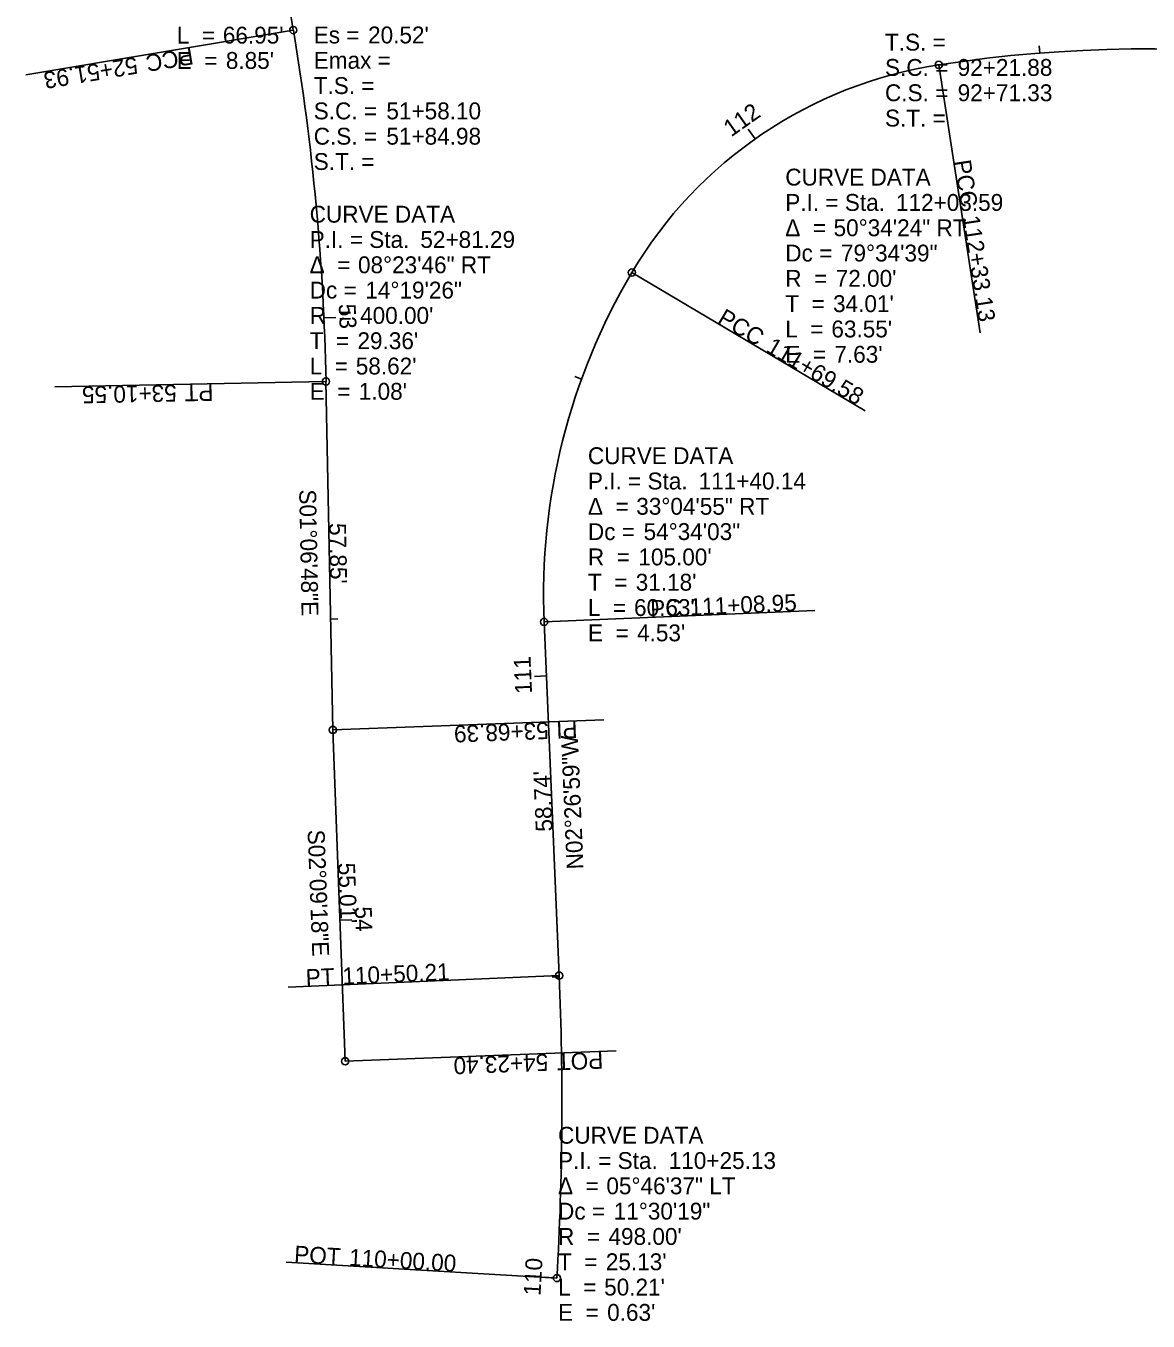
# Model space of a CAD drawing. Extents: x 2047391 to 2047982, y 456752 to 457262.
# Drawn here: x 2047571.9 to 2047758.1, y 456752.1 to 456967.1 of the extents above; entities that cross this region are included whole.
import ezdxf

# ---------------------------------------------------------------- set-up
doc = ezdxf.new("R2010")
doc.units = 0
for name, color, linetype in [('GE_P_Alignment', 7, 'Continuous'), ('GE_P_Alignment_100_Bearings', 7, 'Continuous'), ('GE_P_Alignment_100_Cardinal_Points', 7, 'Continuous'), ('GE_P_Alignment_100_Curve_Data', 7, 'Continuous'), ('GE_P_Alignment_100_Distances', 7, 'Continuous'), ('GE_P_Alignment_100_Stations', 7, 'Continuous')]:
    doc.layers.add(name, color=color, linetype=linetype)

msp = doc.modelspace()

# ---------------------------------------------------------------- linework, layer by layer
at = {"layer": 'GE_P_Alignment'}
for p, q in [((2047621.7, 456908.06), (2047622.83, 456850.23)), ((2047660.4, 456809.46), (2047657.89, 456868.15)), ((2047660.4, 456809.46), (2047657.89, 456868.15)), ((2047622.83, 456850.23), (2047624.89, 456795.25))]:
    msp.add_line(p, q, dxfattribs=at)
for centre, radius, start, end in [((2047547.24, 456954.81), 70, 9.5095, 64.3115), ((2047221.78, 456900.29), 400, 1.1135, 9.5095), ((2047757.79, 456738.25), 225, 66.2355, 98.7946), ((2047757.79, 456738.25), 225, 66.2355, 98.7946), ((2047734.4, 456889.45), 72, 98.7946, 149.3679), ((2047734.4, 456889.45), 72, 98.7946, 149.3679), ((2047762.8, 456872.63), 105, 149.3679, 182.4498), ((2047762.8, 456872.63), 105, 149.3679, 182.4498), ((2047762.8, 456872.63), 105, 149.3679, 182.4498), ((2047162.86, 456788.17), 498, 356.6728, 2.4498), ((2047162.86, 456788.17), 498, 356.6728, 2.4498)]:
    msp.add_arc(centre, radius, start, end, dxfattribs=at)
at = {"layer": 'GE_P_Alignment_100_Cardinal_Points'}
for p, q in [((2047616.28, 456966.37), (2047571.9, 456958.94)), ((2047723.39, 456960.6), (2047730.27, 456916.13)), ((2047672.45, 456926.13), (2047711.17, 456903.21)), ((2047621.7, 456908.06), (2047576.71, 456907.19)), ((2047657.89, 456868.15), (2047702.85, 456870.07)), ((2047622.83, 456850.23), (2047667.79, 456851.92)), ((2047660.4, 456809.46), (2047615.44, 456807.54)), ((2047624.89, 456795.25), (2047669.86, 456796.95)), ((2047660.02, 456759.27), (2047615.09, 456761.88))]:
    msp.add_line(p, q, dxfattribs=at)
for centre in [(2047616.28, 456966.37), (2047723.39, 456960.6), (2047672.45, 456926.13), (2047621.7, 456908.06), (2047657.89, 456868.15), (2047622.83, 456850.23), (2047660.4, 456809.46), (2047624.89, 456795.25), (2047660.02, 456759.27)]:
    msp.add_circle(centre, 0.6, dxfattribs=at)
at = {"layer": 'GE_P_Alignment_100_Stations'}
for p, q in [((2047740.15, 456962.55), (2047740.05, 456963.75)), ((2047692.94, 456948.31), (2047691.79, 456949.95)), ((2047621.36, 456918.6), (2047623.35, 456918.69)), ((2047664.1, 456908.46), (2047662.97, 456908.87)), ((2047622.47, 456868.61), (2047623.67, 456868.64)), ((2047658.27, 456859.2), (2047656.28, 456859.12)), ((2047624.01, 456818.64), (2047626.01, 456818.72)), ((2047660.41, 456809.25), (2047659.21, 456809.2)), ((2047660.02, 456759.27), (2047658.02, 456759.39))]:
    msp.add_line(p, q, dxfattribs=at)

# ---------------------------------------------------------------- texts
at = {"layer": 'GE_P_Alignment_100_Bearings'}
for s, rotation, p in [('S01°06\'48"E', 271.1135, (2047617.25, 456890.12)), ('N02°26\'59"W', 92.4498, (2047664.45, 456827.15)), ('S02°09\'18"E', 272.1551, (2047618.65, 456833.63))]:
    msp.add_text(s, height=2.8, rotation=rotation, dxfattribs=at).set_placement(p)
at = {"layer": 'GE_P_Alignment_100_Cardinal_Points'}
for s, rotation, p in [('PCC', 189.5095, (2047599.41, 456963.5)), ('52+51.93', 189.5095, (2047590.19, 456961.95)), ('PCC', 278.7946, (2047725.91, 456944.63)), ('112+33.13', 278.7946, (2047727.34, 456935.39)), ('PCC', 329.3679, (2047686.5, 456917.87)), ('111+69.58', 329.3679, (2047694.54, 456913.1)), ('53+10.55', 181.1135, (2047596.9, 456907.53)), ('PT', 181.1135, (2047602.99, 456907.65)), ('PC', 2.4498, (2047675.57, 456868.95)), ('111+08.95', 2.4498, (2047682.09, 456869.23)), ('53+68.39', 182.1551, (2047658.61, 456851.53)), ('PI', 182.1551, (2047663.39, 456851.71)), ('PT', 2.4498, (2047618.39, 456807.71)), ('110+50.21', 2.4498, (2047624.48, 456807.97)), ('54+23.40', 182.1551, (2047658.53, 456796.47)), ('POT', 182.1551, (2047667.66, 456796.82)), ('POT', 356.6728, (2047616.36, 456761.86)), ('110+00.00', 356.6728, (2047625.47, 456761.33))]:
    msp.add_text(s, height=2.8, rotation=rotation, dxfattribs=at).set_placement(p)
at = {"layer": 'GE_P_Alignment_100_Curve_Data'}
for s, p in [('L  = ', (2047596.93, 456964.13)), ("66.95'", (2047604.58, 456964.13)), ('Es = ', (2047619.66, 456964.16)), ("20.52'", (2047628.68, 456964.16)), ('T.S. = ', (2047714.47, 456962.97)), ('E  = ', (2047596.93, 456959.93)), ("8.85'", (2047605.08, 456959.93)), ('Emax = ', (2047619.66, 456959.96)), ('S.C. = ', (2047714.47, 456958.77)), ('92+21.88', (2047726.53, 456958.77)), ('T.S. = ', (2047619.66, 456955.76)), ('C.S. = ', (2047714.47, 456954.57)), ('92+71.33', (2047726.53, 456954.57)), ('S.C. = ', (2047619.66, 456951.56)), ('51+58.10', (2047631.72, 456951.56)), ('S.T. = ', (2047714.47, 456950.37)), ('C.S. = ', (2047619.66, 456947.36)), ('51+84.98', (2047631.72, 456947.36)), ('S.T. = ', (2047619.66, 456943.16)), ('CURVE DATA', (2047697.92, 456940.57)), ('P.I. = Sta. ', (2047697.92, 456936.37)), ('112+03.59', (2047716.29, 456936.37)), ('CURVE DATA', (2047618.99, 456934.42)), ('P.I. = Sta. ', (2047618.99, 456930.22)), ('52+81.29', (2047637.36, 456930.22)), ('Δ  = ', (2047697.92, 456932.17)), ('50°34\'24" RT', (2047705.94, 456932.17)), ('Δ  = ', (2047618.99, 456926.02)), ('08°23\'46" RT', (2047627.01, 456926.02)), ('Dc = ', (2047697.92, 456927.97)), ('79°34\'39"', (2047707.16, 456927.97)), ("72.00'", (2047706.29, 456923.77)), ('Dc = ', (2047618.99, 456921.82)), ('14°19\'26"', (2047628.23, 456921.82)), ('R  = ', (2047697.92, 456923.77)), ('T  = ', (2047697.92, 456919.57)), ("34.01'", (2047705.85, 456919.57)), ('R  = ', (2047618.99, 456917.62)), ("400.00'", (2047627.36, 456917.62)), ('L  = ', (2047697.92, 456915.37)), ("63.55'", (2047705.57, 456915.37)), ('T  = ', (2047618.99, 456913.42)), ("29.36'", (2047626.92, 456913.42)), ('E  = ', (2047697.92, 456911.17)), ("7.63'", (2047706.07, 456911.17)), ('L  = ', (2047618.99, 456909.22)), ("58.62'", (2047626.64, 456909.22)), ('E  = ', (2047618.99, 456905.02)), ("1.08'", (2047627.14, 456905.02)), ('CURVE DATA', (2047665.17, 456894.34)), ('P.I. = Sta. ', (2047665.17, 456890.14)), ('111+40.14', (2047683.54, 456890.14)), ('Δ  = ', (2047665.17, 456885.94)), ('33°04\'55" RT', (2047673.19, 456885.94)), ('Dc = ', (2047665.17, 456881.74)), ('54°34\'03"', (2047674.41, 456881.74)), ('R  = ', (2047665.17, 456877.54)), ("105.00'", (2047673.54, 456877.54)), ('T  = ', (2047665.17, 456873.34)), ("31.18'", (2047673.1, 456873.34)), ('L  = ', (2047665.17, 456869.14)), ("60.63'", (2047672.82, 456869.14)), ('E  = ', (2047665.17, 456864.94)), ("4.53'", (2047673.32, 456864.94)), ('CURVE DATA', (2047660.21, 456781.57)), ('P.I. = Sta. ', (2047660.21, 456777.37)), ('110+25.13', (2047678.58, 456777.37)), ('Δ  = ', (2047660.21, 456773.17)), ('05°46\'37" LT', (2047668.23, 456773.17)), ('Dc = ', (2047660.21, 456768.97)), ('11°30\'19"', (2047669.45, 456768.97)), ('R  = ', (2047660.21, 456764.77)), ("498.00'", (2047668.58, 456764.77)), ('T  = ', (2047660.21, 456760.57)), ("25.13'", (2047668.14, 456760.57)), ('L  = ', (2047660.21, 456756.37)), ("50.21'", (2047667.86, 456756.37)), ('E  = ', (2047660.21, 456752.17)), ("0.63'", (2047668.36, 456752.17))]:
    msp.add_text(s, height=2.8, dxfattribs=at).set_placement(p)
at = {"layer": 'GE_P_Alignment_100_Distances'}
for s, rotation, p in [("57.85'", 271.1135, (2047622.21, 456884.54)), ("58.74'", 92.4498, (2047659.33, 456833.41)), ("55.01'", 272.1551, (2047623.7, 456828.14))]:
    msp.add_text(s, height=2.8, rotation=rotation, dxfattribs=at).set_placement(p)
at = {"layer": 'GE_P_Alignment_100_Stations'}
for s, rotation, p in [('112', 35.1584, (2047688.94, 456948.56)), ('53', 272.6241, (2047623.8, 456920.89)), ('111', 92.4498, (2047655.9, 456856.28)), ('54', 272.1551, (2047626.48, 456820.89)), ('110', 86.6728, (2047657.29, 456756.29))]:
    msp.add_text(s, height=2.8, rotation=rotation, dxfattribs=at).set_placement(p)

doc.saveas('drawing.dxf')
